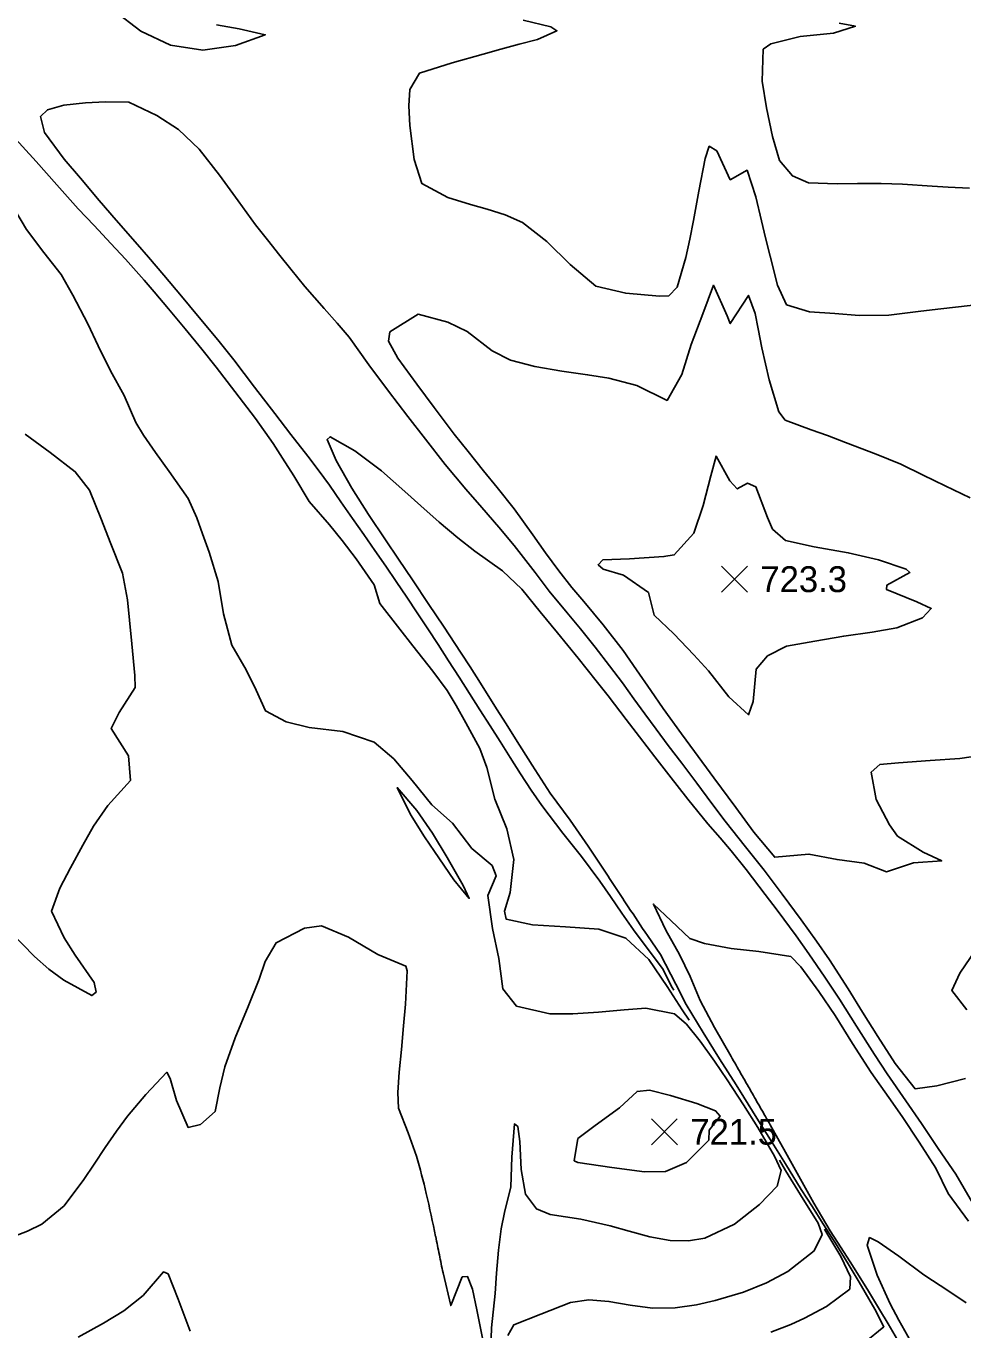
# Model space of a CAD drawing. Extents: x 2566079 to 2571326, y 424054 to 426896.
# Drawn here: x 2570038 to 2570581, y 424461 to 425217 of the extents above; entities that cross this region are included whole.
import ezdxf

# ---------------------------------------------------------------- set-up
doc = ezdxf.new("R2010")
doc.units = 0
for name, color, linetype in [('Contour_ADS_Major', 7, 'Continuous'), ('Contour_ADS_Minor', 7, 'Continuous'), ('Contour_ADS_Spot_Elevation', 7, 'Continuous')]:
    doc.layers.add(name, color=color, linetype=linetype)

# ---------------------------------------------------------------- blocks, each defined once
blk = doc.blocks.new('S750')
at = {"layer": 'Contour_ADS_Spot_Elevation'}
for p, q in [((-0.5, 0.498), (0.5, -0.498)), ((-0.498, -0.5), (0.498, 0.5))]:
    blk.add_line(p, q, dxfattribs=at)

msp = doc.modelspace()

# ---------------------------------------------------------------- linework, layer by layer
at = {"layer": 'Contour_ADS_Major'}
for points in [[(2570509.27, 425218.48), (2570518.79, 425216.63), (2570506.01, 425212.64), (2570486.75, 425210.66), (2570469.76, 425206.57), (2570465.34, 425203.37), (2570464.68, 425184.87), (2570467.33, 425169.44), (2570470.66, 425152.89), (2570474.8, 425138.95), (2570482.26, 425130), (2570491.6, 425125.94), (2570508.1, 425125.37), (2570519.93, 425125.51), (2570533.62, 425125.49), (2570546.14, 425125.25), (2570563.24, 425124.1), (2570572.43, 425123.44), (2570584.86, 425122.91)], [(2570586.53, 424535), (2570576.99, 424551.66), (2570566.72, 424566.47), (2570557.06, 424581.05), (2570547.88, 424594.19), (2570537.09, 424609.7), (2570529.73, 424620.9), (2570519.34, 424637.39), (2570509.61, 424653.06), (2570501.13, 424665.88), (2570491.84, 424679.34), (2570484.4, 424689.82), (2570473.41, 424704.53), (2570466.47, 424713.67), (2570455.53, 424728.08), (2570446.78, 424738.99), (2570440.44, 424746.43), (2570433.34, 424754.7), (2570421.62, 424768.81), (2570410.76, 424782.91), (2570402.61, 424793.48), (2570393.69, 424805.03), (2570385.92, 424815.15), (2570375.59, 424828.76), (2570368.65, 424837.55), (2570358.1, 424850.61), (2570346.21, 424865.21), (2570336.22, 424877.43), (2570325.45, 424890.58), (2570314.22, 424901.12), (2570298.37, 424912.63), (2570288.37, 424920.29), (2570277.57, 424929.37), (2570266.97, 424938.79), (2570257.71, 424947.22), (2570244.15, 424959.14), (2570228.68, 424970.79), (2570214.38, 424978.84), (2570212.64, 424977.19), (2570217.87, 424965.04), (2570226.97, 424949.09), (2570236.66, 424933.72), (2570246.62, 424919.16), (2570254.12, 424908.02), (2570262.19, 424895.94), (2570271.69, 424881.69), (2570280.11, 424869.07), (2570290.4, 424853.55), (2570295.49, 424845.54), (2570301.47, 424836.08), (2570310.9, 424821.15), (2570316.34, 424812.54), (2570321.79, 424803.92), (2570331.47, 424788.61), (2570341.86, 424772.35), (2570353.5, 424756.82), (2570363.98, 424741.58), (2570374.69, 424725.39)], [(2570398.3, 424689.85), (2570405.89, 424678.83), (2570414.71, 424661.76), (2570420.81, 424650), (2570430.5, 424633.69), (2570439.95, 424618.55), (2570449.76, 424603.38), (2570454.18, 424596.31), (2570461.74, 424584.18), (2570470.59, 424569.97), (2570478.2, 424557.72), (2570487.31, 424542.87), (2570493.81, 424532.68), (2570499.95, 424523.12), (2570507.28, 424511.61), (2570514.62, 424499.81), (2570520.97, 424489.15), (2570529.93, 424473.41), (2570535.28, 424463.28), (2570523.79, 424453.86)]]:
    msp.add_lwpolyline(points, dxfattribs=at)
for centre, radius, start, end in [((2548391.82, 410187.97), 26354.94, 33.4524, 33.476922), ((2573948.41, 427067.33), 4272.7, 213.38903, 213.54029), ((2572661.98, 426214.22), 2729.09, 213.53431, 213.95647)]:
    msp.add_arc(centre, radius, start, end, dxfattribs=at)
at = {"layer": 'Contour_ADS_Minor'}
for points in [[(2570148.6, 425217.44), (2570161.82, 425215.15), (2570176.86, 425211.72), (2570159.63, 425205.5), (2570140.68, 425202.8), (2570121.95, 425205.7), (2570104.72, 425213.76), (2570089.19, 425225.87)], [(2569968.98, 425219.14), (2569979.4, 425208.36), (2569986.18, 425201.2), (2569994.63, 425192.16), (2570004.91, 425181.1), (2570016.05, 425169.05), (2570026.81, 425157.34), (2570036.18, 425147.07), (2570044.06, 425138.34), (2570056.07, 425124.81), (2570068.57, 425110.94), (2570077.66, 425101.2), (2570087.46, 425090.77), (2570095.99, 425081.64)], [(2570326.28, 425220.18), (2570342.36, 425216.42), (2570345.84, 425214.09), (2570334.52, 425208.97), (2570323.99, 425206.21), (2570313.33, 425203.33), (2570303.16, 425200.47), (2570285.07, 425195.43), (2570266.15, 425189.41), (2570260.55, 425180.07), (2570260.04, 425170.54), (2570260.62, 425159.16), (2570263.12, 425139.49), (2570267.62, 425125.5), (2570282.57, 425117.44), (2570295.74, 425113.42), (2570305.39, 425110.75), (2570315.94, 425107.35), (2570325.86, 425102.97), (2570339.96, 425091.97), (2570353.59, 425078.59), (2570368.37, 425066.05), (2570385.7, 425061.96), (2570405.31, 425060.32), (2570410.67, 425060.44), (2570415.56, 425065.53), (2570420.46, 425082.65), (2570422.82, 425093.39), (2570425.02, 425104.18), (2570428.07, 425121.12), (2570431.69, 425140.09), (2570434.1, 425147.12), (2570438.42, 425144.43), (2570446.24, 425127.73), (2570456, 425133.29), (2570460.99, 425117.87), (2570464.32, 425103.95), (2570466.75, 425094.01), (2570469.34, 425083.46), (2570473.53, 425066.76), (2570478.85, 425055.29), (2570492.23, 425051.23), (2570506.83, 425050.29), (2570521, 425049.05), (2570538.18, 425049.31), (2570555.15, 425051.45), (2570566.57, 425052.83), (2570578.56, 425054.19), (2570590.25, 425055.39)], [(2570072.7, 425172.29), (2570060.22, 425170.91), (2570050.62, 425168.32), (2570046.6, 425164.31), (2570048.89, 425155.16), (2570060.35, 425139.72), (2570069.76, 425128.58), (2570080.71, 425115.78), (2570090.54, 425104.4), (2570102.92, 425090.31), (2570109.3, 425082.91), (2570118.19, 425072.38), (2570128.28, 425060.3), (2570137.58, 425049.17), (2570149.35, 425035.08), (2570158.73, 425023.33), (2570170.71, 425007.57), (2570182.32, 424992.28), (2570191.74, 424980.09), (2570201.61, 424967.55), (2570207.56, 424959.69), (2570214.01, 424950.79), (2570220.74, 424941.24), (2570227.49, 424931.56), (2570234.05, 424922.16), (2570240.42, 424913), (2570246.65, 424903.95), (2570252.78, 424894.92), (2570258.86, 424885.87), (2570264.91, 424876.79), (2570270.96, 424867.67), (2570277.04, 424858.46), (2570283.12, 424849.12), (2570289.22, 424839.64), (2570295.28, 424830.11), (2570301.24, 424820.69), (2570307.07, 424811.46), (2570312.87, 424802.29), (2570318.76, 424793.02), (2570324.82, 424783.55), (2570331, 424774.15), (2570337.19, 424765.16), (2570349.23, 424749.22), (2570360.04, 424735.66), (2570370.7, 424721.39), (2570376.83, 424712.5), (2570383.45, 424702.83), (2570390.28, 424693.14), (2570396.98, 424684.19), (2570407.05, 424670.85), (2570412.57, 424659.85), (2570413.56, 424658.2)], [(2570582.53, 424607.08), (2570565.93, 424602.92), (2570553.29, 424601.13), (2570541.81, 424615.74), (2570531.67, 424631.5), (2570522.91, 424645.49), (2570514.55, 424659.12), (2570503.79, 424675.81), (2570496.22, 424686.63), (2570487.4, 424699), (2570476.41, 424713.81), (2570465.92, 424727.77), (2570455.15, 424741.38), (2570443.38, 424756.08), (2570435.51, 424766.45), (2570426.8, 424778.14), (2570418.17, 424789.72), (2570410.34, 424800.08), (2570403.26, 424809.41), (2570396.7, 424818.25), (2570390.35, 424827.09), (2570383.76, 424836.3), (2570376.39, 424846.24), (2570368.02, 424856.99), (2570359.47, 424867.59), (2570351.85, 424876.82), (2570341.37, 424889.35), (2570333.17, 424900.13), (2570321.14, 424915.79), (2570312.13, 424926.51), (2570302.24, 424937.94), (2570293.14, 424948.43), (2570281.13, 424962.75), (2570269.67, 424977.46), (2570259.52, 424990.53), (2570248.22, 425005.27), (2570236.81, 425020.54), (2570225.4, 425036.55), (2570218.55, 425044.65), (2570211.01, 425053.2), (2570199.78, 425065.96), (2570191.65, 425075.98), (2570185.37, 425083.81), (2570178.12, 425092.91), (2570171.31, 425101.67), (2570161.25, 425115.46), (2570150.4, 425130.34), (2570138.64, 425145.43), (2570126.59, 425156.9), (2570114.03, 425164.98), (2570097.84, 425172.69), (2570084.35, 425172.93), (2570072.7, 425172.29)], [(2570028.75, 425115.47), (2570038.62, 425098.84), (2570048.59, 425085.67), (2570058.56, 425072.84), (2570065.33, 425060.96), (2570074.05, 425044.24), (2570080.04, 425031.5), (2570087.29, 425017.05), (2570095.05, 425002.69), (2570101.94, 424987.15), (2570106.31, 424979.78), (2570113.25, 424969.7), (2570121.17, 424958.78), (2570132.21, 424943.09), (2570137.19, 424931.89), (2570140.59, 424922.65), (2570144.42, 424911.94), (2570149.66, 424895.09), (2570152.58, 424876.2), (2570157.42, 424858.06), (2570165.75, 424843.76), (2570171.57, 424832.04), (2570176.93, 424820.05), (2570188.9, 424813.64), (2570202.38, 424810.42), (2570221.85, 424808.14), (2570239.9, 424801.91), (2570251.35, 424792.35), (2570262.06, 424779.77), (2570273.42, 424765.55), (2570285.43, 424754.96), (2570296.62, 424740.31), (2570308.24, 424730.45), (2570310.58, 424724.57), (2570305.9, 424713.09), (2570308.54, 424694.02), (2570312.11, 424676.59), (2570314.59, 424659.08), (2570322.37, 424649.08), (2570341.67, 424644.59), (2570355.05, 424644.51), (2570369.97, 424645.51), (2570384.74, 424646.87), (2570397.44, 424647.76), (2570413.94, 424644.56), (2570420.84, 424638.52), (2570428.8, 424628.75), (2570437.08, 424617.17), (2570444.46, 424606.25), (2570453.99, 424591.79), (2570462.32, 424578.6), (2570471.94, 424562.08), (2570475.77, 424553.81), (2570473.35, 424544.69), (2570463.28, 424534.08), (2570448.77, 424522.71)], [(2570095.99, 425081.64), (2570106.77, 425069.57), (2570112.55, 425062.74), (2570120.77, 425052.97), (2570130.48, 425041.35), (2570140.13, 425029.6), (2570148.39, 425019.26), (2570159.33, 425005.06), (2570171.13, 424989.5), (2570181.36, 424975.04), (2570186.88, 424966.41), (2570193.33, 424956.21), (2570202.37, 424941.28), (2570214.18, 424927.91), (2570221.49, 424918.83), (2570229.61, 424908.12), (2570239.92, 424892.99), (2570243.21, 424882.27), (2570254.87, 424867.32), (2570262.27, 424857.8), (2570273.87, 424842.96), (2570282.31, 424831.86), (2570287.4, 424823.17), (2570292.98, 424813.21), (2570301.13, 424798.18), (2570305.2, 424787.2), (2570309.93, 424768.99), (2570316.81, 424751.79), (2570320.92, 424733.98), (2570318.69, 424714.87), (2570315.54, 424704.1), (2570316.35, 424699.48), (2570331.77, 424696.09), (2570350.83, 424694.92), (2570370.2, 424693.64), (2570385.67, 424688.4), (2570399, 424676.1), (2570409.68, 424660.41), (2570418.48, 424646.83), (2570422.48, 424640.84)], [(2570598.94, 424795.37), (2570579.32, 424792.37), (2570562.08, 424791.31), (2570543.81, 424789.97), (2570532.97, 424788.99), (2570527.93, 424784.56), (2570530.86, 424768.67), (2570538.43, 424754.06), (2570543.11, 424747.56), (2570558.09, 424738.2), (2570568.81, 424733.17), (2570552.48, 424732.02), (2570536.75, 424726.84), (2570523.8, 424731.88), (2570508.14, 424733.89), (2570491.86, 424737.1), (2570471.99, 424735.25), (2570459.97, 424749.71), (2570449.41, 424764.09), (2570436.82, 424781.24), (2570425.57, 424796.53), (2570418.06, 424806.67), (2570407.48, 424821.35), (2570400.22, 424831.84), (2570391.93, 424843.84), (2570384.13, 424854.93), (2570372.72, 424869.98), (2570361.37, 424883.32), (2570354.45, 424891.6), (2570346.96, 424901.12), (2570339.23, 424911.69), (2570331.94, 424922.11), (2570321.16, 424937.17), (2570311.23, 424949.44), (2570303.33, 424959.19), (2570294.42, 424970.28), (2570286.38, 424980.42), (2570274.66, 424995.76), (2570264.68, 425009.3), (2570253.65, 425024.39), (2570248.2, 425034.19), (2570248.98, 425039.57), (2570265.39, 425049.93), (2570282.66, 425045.3), (2570293.88, 425039.74), (2570308.26, 425028.63), (2570318.93, 425023.3), (2570332.98, 425019.51), (2570348.66, 425016.9), (2570363.59, 425014.82), (2570375.85, 425012.71), (2570392.17, 425008.55), (2570409.7, 424999.95), (2570418.28, 425014.87), (2570423.68, 425032.28), (2570430.28, 425049.99), (2570436.5, 425066.62), (2570444.47, 425048.97), (2570446.23, 425044.39), (2570456.86, 425060.7), (2570460.66, 425050.3), (2570462.41, 425041.32), (2570464.6, 425030.42), (2570468.85, 425011.82), (2570474.49, 424993.2), (2570478.09, 424988.37), (2570493.17, 424982.86), (2570502.56, 424979.53), (2570513.02, 424975.61), (2570530.78, 424968.76), (2570545.01, 424962.91), (2570558.01, 424956.6), (2570570.75, 424950.39), (2570585.15, 424943.39)], [(2570037.74, 424980.42), (2570052.26, 424969.68), (2570066.74, 424958.55), (2570075.09, 424947.86), (2570081.95, 424930.73), (2570087, 424917.88), (2570094.09, 424899.74), (2570097.06, 424884.33), (2570098.19, 424872.58), (2570099.52, 424858.83), (2570101.35, 424840.45), (2570101.51, 424833.67), (2570092.27, 424819.05), (2570087.57, 424809.79), (2570097.61, 424794.05), (2570098.84, 424779.74), (2570085.76, 424765.32), (2570077.36, 424753.3), (2570071.16, 424742.18), (2570064.02, 424729.03), (2570057.79, 424717.35), (2570053.12, 424703.99), (2570060.4, 424688.6), (2570066.76, 424678.56), (2570077.66, 424662.77), (2570078.88, 424657.14), (2570076.32, 424655.08), (2570060.17, 424663.95), (2570051.58, 424670.4), (2570043.15, 424677.69), (2570029.29, 424691.95)], [(2570412.1, 424698.43), (2570401.78, 424708.14), (2570408.95, 424692.94), (2570416.81, 424678.83), (2570422.94, 424666.24), (2570428.8, 424652.29), (2570437.22, 424636.56), (2570446.69, 424619.91)], [(2570264.54, 424562.15), (2570259.75, 424575.53), (2570254.11, 424589.82), (2570253.72, 424599.03), (2570254.5, 424610.75), (2570255.79, 424623.96), (2570257.03, 424637.57), (2570258.04, 424650.1), (2570259.13, 424669.41), (2570258.38, 424672.14), (2570242.04, 424678.9), (2570225.17, 424689.01), (2570209.37, 424695.45), (2570199.67, 424694.15), (2570183.09, 424685.76), (2570176.77, 424674.91), (2570173.26, 424664.56), (2570166.95, 424648.81), (2570159.52, 424630.58), (2570153.5, 424613.86), (2570150.61, 424601.74), (2570147.81, 424587.94), (2570139.3, 424580.34), (2570132.15, 424578.74), (2570125.45, 424594.37), (2570121.78, 424606.99), (2570119.77, 424610.74), (2570107.76, 424597.85), (2570097.05, 424585.2), (2570090.7, 424576.66), (2570084.11, 424567.15), (2570077.68, 424557.51), (2570071.69, 424548.5), (2570060.33, 424533.4), (2570047.49, 424522.75), (2570039.12, 424518.55), (2570029.04, 424514.75)], [(2570584.2, 424524.51), (2570572.5, 424540.43), (2570565.29, 424555.14), (2570555.67, 424570.14), (2570545.92, 424585.02), (2570538.06, 424596.16), (2570527.9, 424610.55), (2570517.04, 424627.29), (2570506.96, 424643.52), (2570497.48, 424657.48), (2570487.08, 424671.75), (2570481.28, 424677.82), (2570462.85, 424680.69), (2570446.88, 424682.46), (2570431.34, 424685.22), (2570422.79, 424688.26), (2570412.1, 424698.43)], [(2570588.33, 424681.45), (2570579.32, 424668.17), (2570574.71, 424657.99), (2570583.36, 424646.82)], [(2570448.77, 424522.71), (2570431.58, 424514.66), (2570421.98, 424513.02), (2570411.37, 424513.28), (2570399.7, 424515.43), (2570387.78, 424518.62), (2570376.65, 424521.78), (2570359.73, 424525.5), (2570341.94, 424528.21), (2570333.97, 424531.48), (2570327.72, 424540.02), (2570325.22, 424554.36), (2570324.44, 424570.62), (2570323.11, 424579.33), (2570321.21, 424580.79), (2570319.63, 424561.46), (2570319.06, 424544.25), (2570315.49, 424529.38), (2570313.48, 424519.98), (2570311.96, 424507.67), (2570310.9, 424494.31), (2570310.11, 424482.49), (2570308.01, 424462.68), (2570307.37, 424444.33)], [(2570469.43, 424580.16), (2570478.33, 424564.41), (2570485.08, 424552.32), (2570494.77, 424534.9), (2570504.22, 424518.91), (2570510.48, 424508.95), (2570517, 424498.71), (2570526.33, 424483.92), (2570532.78, 424473.19), (2570537.74, 424464.97), (2570543.21, 424455.63), (2570550.51, 424440.84), (2570554.9, 424426.07), (2570553.19, 424418.4), (2570541.86, 424404.25), (2570535.8, 424397.47), (2570527.1, 424387.86), (2570515.28, 424374.39)], [(2570474.7, 424559.75), (2570478.27, 424553.74), (2570486.92, 424539.73), (2570497.2, 424523.34), (2570499.51, 424516.7), (2570494.81, 424507.2), (2570479.64, 424495.35), (2570467.16, 424488.65), (2570454.02, 424483.27), (2570437.58, 424478.44), (2570426.64, 424476.04), (2570414.27, 424474.32), (2570401.27, 424474.1), (2570388.36, 424475.78), (2570375.93, 424477.98), (2570364.32, 424478.89), (2570353.78, 424477.25), (2570336.45, 424470.57), (2570320.89, 424464.46), (2570317.35, 424458.25)], [(2570500.8, 424519.75), (2570501.63, 424518.45), (2570510.38, 424503.9), (2570515.87, 424492.26), (2570515.46, 424485.13), (2570502.04, 424475.07), (2570489.32, 424468.21), (2570481.31, 424464.64), (2570469.77, 424460.18)], [(2570582.95, 424477.05), (2570572.95, 424483.92), (2570558.33, 424493.34), (2570543.9, 424504.16), (2570531.95, 424512.54), (2570527.01, 424514.9), (2570525.61, 424510.49), (2570531.38, 424493.11), (2570538.91, 424476.52), (2570543.99, 424467), (2570549.09, 424457.74), (2570557.53, 424442.45), (2570565.85, 424427.37), (2570575.67, 424409.99), (2570582.7, 424397.36)], [(2570133.29, 424460.8), (2570126.48, 424479.34), (2570120.59, 424493.96), (2570117.99, 424495.08), (2570106.05, 424481.42), (2570095.02, 424472.52), (2570083.1, 424465.36), (2570068.5, 424457.28)], [(2570303.18, 424454.68), (2570299.44, 424473.13), (2570296.84, 424484.97), (2570293.96, 424492.42), (2570290.99, 424492.1), (2570284.33, 424475.55), (2570279.86, 424494.47)]]:
    msp.add_lwpolyline(points, dxfattribs=at)
for points in [[(2570402.14, 424875.55), (2570398.92, 424888.6), (2570384.45, 424898.65), (2570372.58, 424902.1), (2570369.67, 424904.72), (2570372.37, 424907.54), (2570387.98, 424908.1), (2570407.86, 424909.39), (2570413.77, 424910.42), (2570425.18, 424923.09), (2570430.48, 424939.09), (2570434.91, 424956.18), (2570438.01, 424967.68), (2570445.92, 424953.34), (2570450.27, 424948.59), (2570456.2, 424951.92), (2570461, 424949.93), (2570467.79, 424932), (2570470.68, 424925.39), (2570478.21, 424918.66), (2570494.95, 424915.1), (2570514.62, 424911.67), (2570532.12, 424907.6), (2570548.24, 424902.19), (2570550.31, 424900.27), (2570537, 424892.88), (2570536.73, 424890.37), (2570554.26, 424883.2), (2570562.69, 424879.4), (2570557.66, 424873.96), (2570542.78, 424868.13), (2570528.42, 424865.74), (2570512.04, 424863.42), (2570495.19, 424860.39), (2570478.91, 424857.5), (2570467.79, 424851.86), (2570461.24, 424844.12), (2570459.53, 424825.49), (2570456.87, 424817.82), (2570445.48, 424828.22), (2570433.71, 424843.23), (2570425.23, 424852.54), (2570413.56, 424864.67), (2570402.14, 424875.55)], [(2570269.15, 424747.14), (2570260.95, 424759.95), (2570253.29, 424775.58), (2570264.63, 424762.26), (2570273.79, 424749.28), (2570282.25, 424735.17), (2570291.56, 424718.92), (2570295.01, 424711.36), (2570286.15, 424722.19), (2570274.9, 424738.6), (2570269.15, 424747.14)], [(2570408.68, 424553.16), (2570396.6, 424553.06), (2570377.69, 424555.56), (2570358.02, 424558.34), (2570355.84, 424559.44), (2570357.95, 424572.26), (2570367.94, 424579.93), (2570382.03, 424590.02), (2570392.31, 424599.58), (2570399.47, 424600.4), (2570411.72, 424597.18), (2570426.92, 424592.57), (2570437.78, 424588.41), (2570440.34, 424585.34), (2570434.08, 424577.07), (2570433.92, 424571.36), (2570420.87, 424558.4), (2570408.68, 424553.16)]]:
    msp.add_lwpolyline(points, close=True, dxfattribs=at)
for centre, radius, start, end in [((2576911.12, 428320), 7448.45, 209.785817, 209.875197), ((2550112.61, 412971.72), 23434.06, 29.749014, 29.777433), ((2550065.21, 412928.18), 23496.83, 29.756333, 29.783836), ((2566556.89, 422352.63), 4502.21, 29.65423, 29.7977), ((2569851.89, 424444.41), 429.12, 12.92834, 15.92451), ((2569184.06, 424289.49), 1114.68, 11.69756, 13.00939), ((2568739.22, 424197.19), 1569, 11.31315, 11.70482), ((2570912.99, 424628.25), 647.11, 190.98188, 191.93138)]:
    msp.add_arc(centre, radius, start, end, dxfattribs=at)

# ---------------------------------------------------------------- block references
at = {"layer": 'Contour_ADS_Spot_Elevation', "xscale": 15, "yscale": 15}
for p in [(2570448.71, 424896.34), (2570408.12, 424576.2)]:
    msp.add_blockref('S750', p, dxfattribs=at)

# ---------------------------------------------------------------- texts
at = {"layer": 'Contour_ADS_Spot_Elevation'}
for s, p in [('723.3', (2570463.71, 424888.84)), ('721.5', (2570423.12, 424568.7))]:
    msp.add_text(s, height=15, dxfattribs=at).set_placement(p)

doc.saveas('drawing.dxf')
